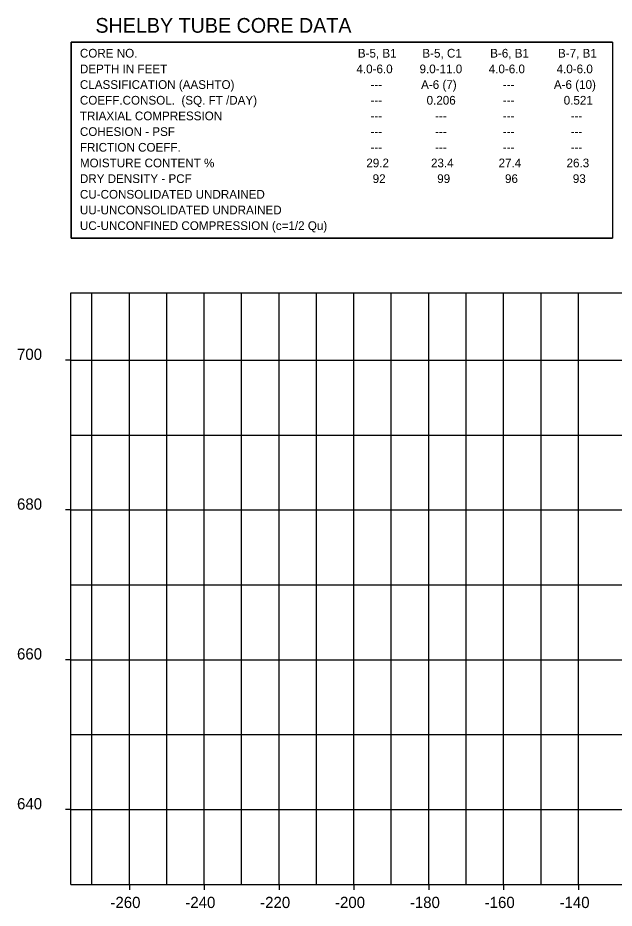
# Model space of a CAD drawing. Extents: x -290 to 297, y 616 to 861.
# Drawn here: x -289.8 to -130.4, y 623.7 to 861.4 of the extents above; entities that cross this region are included whole.
import ezdxf

# ---------------------------------------------------------------- set-up
doc = ezdxf.new("R2010")
doc.units = 0
for name, color, linetype in [('Cell', 7, 'Continuous'), ('DisROW Proposed Temp Easements', 7, 'Continuous'), ('SheetText', 7, 'Continuous'), ('TextAlignment', 7, 'Continuous'), ('TextAlignmentSml', 7, 'Continuous'), ('V-SWLK-CONC', 7, 'Continuous')]:
    doc.layers.add(name, color=color, linetype=linetype)

msp = doc.modelspace()

# ---------------------------------------------------------------- linework, layer by layer
at = {"layer": 'DisROW Proposed Temp Easements'}
for p, q in [((-130.88, 854.87), (-275.57, 854.87)), ((-275.57, 854.87), (-275.57, 802.59)), ((-130.88, 854.87), (-130.88, 802.59)), ((-275.57, 802.59), (-130.88, 802.59))]:
    msp.add_line(p, q, dxfattribs=at)
at = {"layer": 'SheetText'}
for p, q in [((-275.61, 787.99), (284.21, 787.99)), ((-275.61, 630), (-275.61, 787.99)), ((-275.61, 630), (284.21, 630))]:
    msp.add_line(p, q, dxfattribs=at)
at = {"layer": 'TextAlignment'}
for p, q in [((-260, 630), (-260, 787.99)), ((-240, 630), (-240, 787.99)), ((-220, 630), (-220, 787.99)), ((-200, 630), (-200, 787.99)), ((-180, 630), (-180, 787.99)), ((-160, 630), (-160, 787.99)), ((-140, 630), (-140, 787.99)), ((-275.61, 770), (-277.05, 770)), ((-275.61, 770), (284.21, 770)), ((-275.61, 730), (-277.05, 730)), ((-275.61, 730), (284.21, 730)), ((-275.61, 690), (-277.05, 690)), ((-275.61, 690), (284.21, 690)), ((-275.61, 650), (-277.05, 650)), ((-275.61, 650), (284.21, 650)), ((-260, 630), (-260, 628.56)), ((-240, 630), (-240, 628.56)), ((-220, 630), (-220, 628.56)), ((-200, 630), (-200, 628.56)), ((-180, 630), (-180, 628.56)), ((-160, 630), (-160, 628.56)), ((-140, 630), (-140, 628.56))]:
    msp.add_line(p, q, dxfattribs=at)
at = {"layer": 'TextAlignmentSml'}
for p, q in [((-270, 630), (-270, 787.99)), ((-250, 630), (-250, 787.99)), ((-230, 630), (-230, 787.99)), ((-210, 630), (-210, 787.99)), ((-190, 630), (-190, 787.99)), ((-170, 630), (-170, 787.99)), ((-150, 630), (-150, 787.99)), ((-275.61, 750), (284.21, 750)), ((-275.61, 710), (284.21, 710)), ((-275.61, 670), (284.21, 670))]:
    msp.add_line(p, q, dxfattribs=at)
at = {"layer": 'V-SWLK-CONC'}
msp.add_lwpolyline([(-275.57, 854.87), (-130.88, 854.87), (-130.88, 802.59), (-275.57, 802.59)], close=True, dxfattribs=at)

# ---------------------------------------------------------------- texts
at = {"layer": 'Cell'}
for s, p in [('700', (-290.01, 770.06)), ('680', (-290.01, 730.06)), ('660', (-290.01, 690.06)), ('640', (-290.01, 650.06)), ('-260', (-265.05, 623.7)), ('-240', (-245.05, 623.7)), ('-220', (-225.05, 623.7)), ('-200', (-205.05, 623.7)), ('-180', (-185.05, 623.7)), ('-160', (-165.05, 623.7)), ('-140', (-145.05, 623.7))]:
    msp.add_text(s, height=3, dxfattribs=at).set_placement(p)
at = {"layer": 'DisROW Proposed Temp Easements'}
for s, height, p in [('SHELBY TUBE CORE DATA', 3.9355, (-269.07, 857.41)), ('CORE NO.', 2.325, (-273.21, 850.78)), ('B-5, B1', 2.325, (-198.94, 850.78)), ('B-5, C1', 2.325, (-181.7, 850.78)), ('B-6, B1', 2.325, (-163.58, 850.78)), ('B-7, B1', 2.325, (-145.46, 850.78)), ('DEPTH IN FEET', 2.3254, (-273.21, 846.59)), ('4.0-6.0', 2.325, (-199.32, 846.59)), ('9.0-11.0', 2.325, (-182.46, 846.59)), ('4.0-6.0', 2.325, (-163.97, 846.59)), ('4.0-6.0', 2.325, (-145.84, 846.59)), ('CLASSIFICATION (AASHTO)', 2.3254, (-273.21, 842.41)), ('A-6 (7)', 2.325, (-182.04, 842.41)), ('A-6 (10)', 2.325, (-146.56, 842.41)), ('---', 2.325, (-195.56, 842.41)), ('---', 2.325, (-160.21, 842.41)), ('COEFF.CONSOL.  (SQ. FT /DAY)', 2.3254, (-273.21, 838.22)), ('---', 2.325, (-195.56, 838.22)), ('0.206', 2.325, (-180.57, 838.22)), ('---', 2.325, (-160.21, 838.22)), ('0.521', 2.325, (-143.94, 838.22)), ('TRIAXIAL COMPRESSION', 2.3254, (-273.21, 834.04)), ('---', 2.325, (-195.56, 834.04)), ('---', 2.325, (-178.31, 834.04)), ('---', 2.325, (-160.21, 834.04)), ('---', 2.325, (-142.08, 834.04)), ('COHESION - PSF', 2.3254, (-273.21, 829.85)), ('---', 2.325, (-195.56, 829.85)), ('---', 2.325, (-178.31, 829.85)), ('---', 2.325, (-160.21, 829.85)), ('---', 2.325, (-142.08, 829.85)), ('FRICTION COEFF.', 2.3254, (-273.21, 825.66)), ('---', 2.325, (-195.56, 825.66)), ('---', 2.325, (-178.31, 825.66)), ('---', 2.325, (-160.21, 825.66)), ('---', 2.325, (-142.08, 825.66)), ('MOISTURE CONTENT %', 2.3254, (-273.21, 821.48)), ('29.2', 2.325, (-196.68, 821.48)), ('23.4', 2.325, (-179.4, 821.48)), ('27.4', 2.325, (-161.34, 821.48)), ('26.3', 2.325, (-143.18, 821.48)), ('DRY DENSITY - PCF', 2.3254, (-273.21, 817.29)), ('92', 2.325, (-194.98, 817.29)), ('99', 2.325, (-177.73, 817.29)), ('96', 2.325, (-159.63, 817.29)), ('93', 2.325, (-141.5, 817.29)), ('CU-CONSOLIDATED UNDRAINED', 2.3254, (-273.21, 813.11)), ('UU-UNCONSOLIDATED UNDRAINED', 2.3254, (-273.21, 808.92)), ('UC-UNCONFINED COMPRESSION (c=1/2 Qu)', 2.3254, (-273.21, 804.74))]:
    msp.add_text(s, height=height, dxfattribs=at).set_placement(p)

doc.saveas('drawing.dxf')
